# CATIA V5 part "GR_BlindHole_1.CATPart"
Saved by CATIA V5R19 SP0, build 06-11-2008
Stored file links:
  C:\Program Files\Dassault Systemes\Power Feature\SampleData\GeneralData\GeometricalRules\GeomRuleParts\GR_BlindHole_1.CATPart
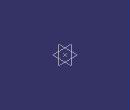
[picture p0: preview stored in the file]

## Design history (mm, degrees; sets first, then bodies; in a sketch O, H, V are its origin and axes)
Set1
  Point1: (0, 0, 0)
Body1 (main body)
